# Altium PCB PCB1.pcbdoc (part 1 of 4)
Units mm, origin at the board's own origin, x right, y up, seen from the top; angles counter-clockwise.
Board outline 77.9 x 109.02 mm, 4 copper layers (Top Layer, Inner1, Inner2, Bottom Layer); 129 components, 135 nets, 715 pads, 425 vias.
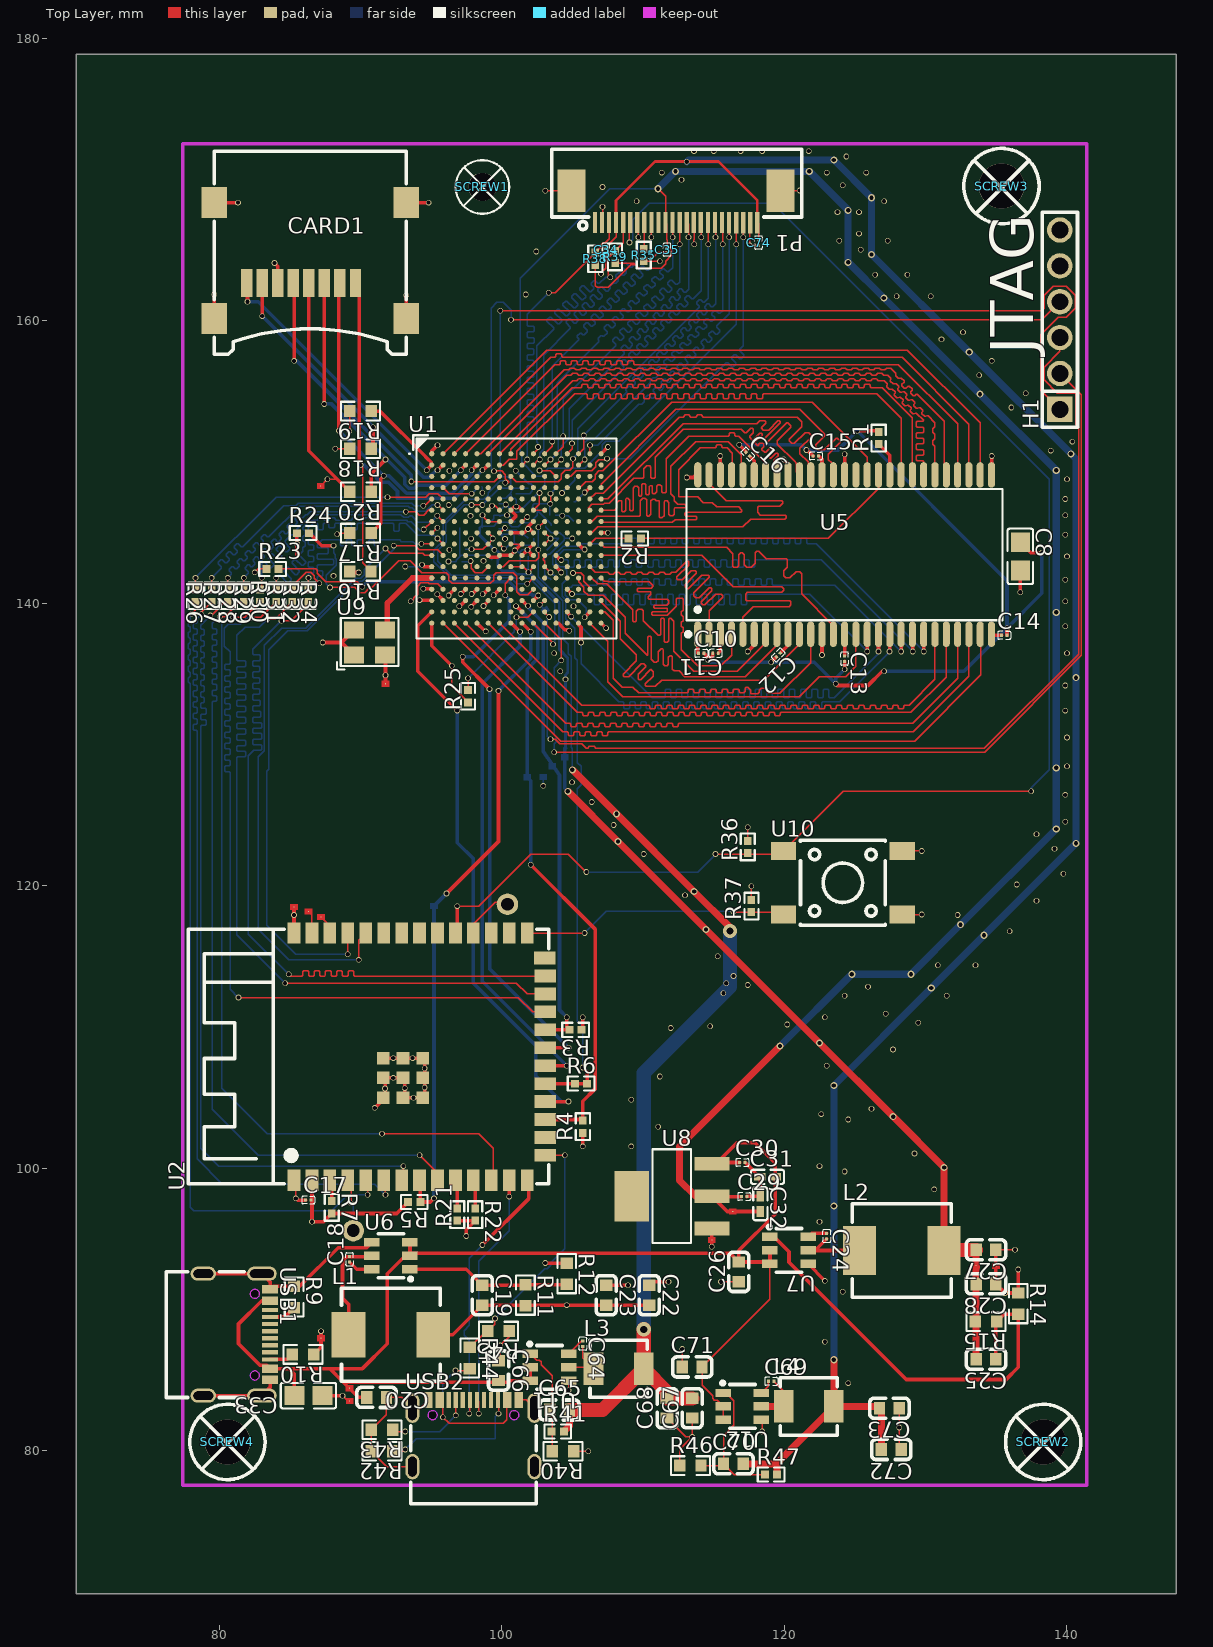
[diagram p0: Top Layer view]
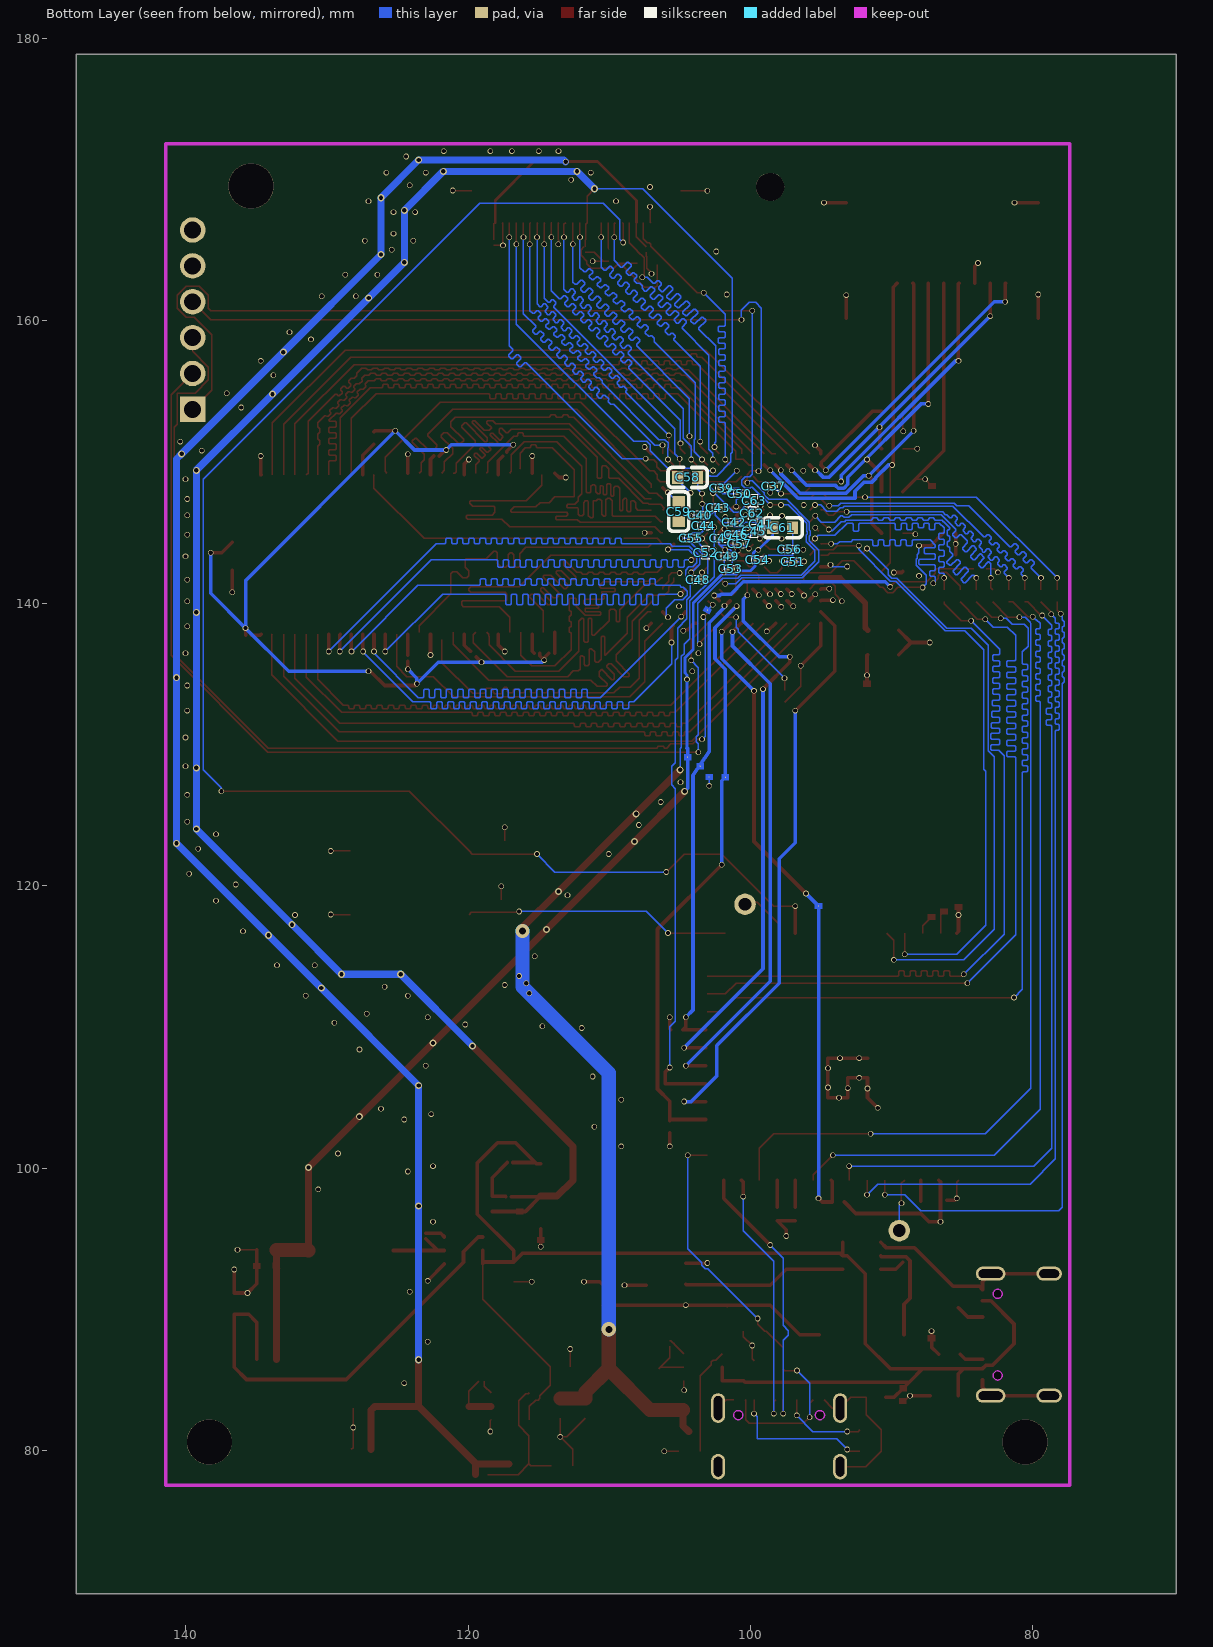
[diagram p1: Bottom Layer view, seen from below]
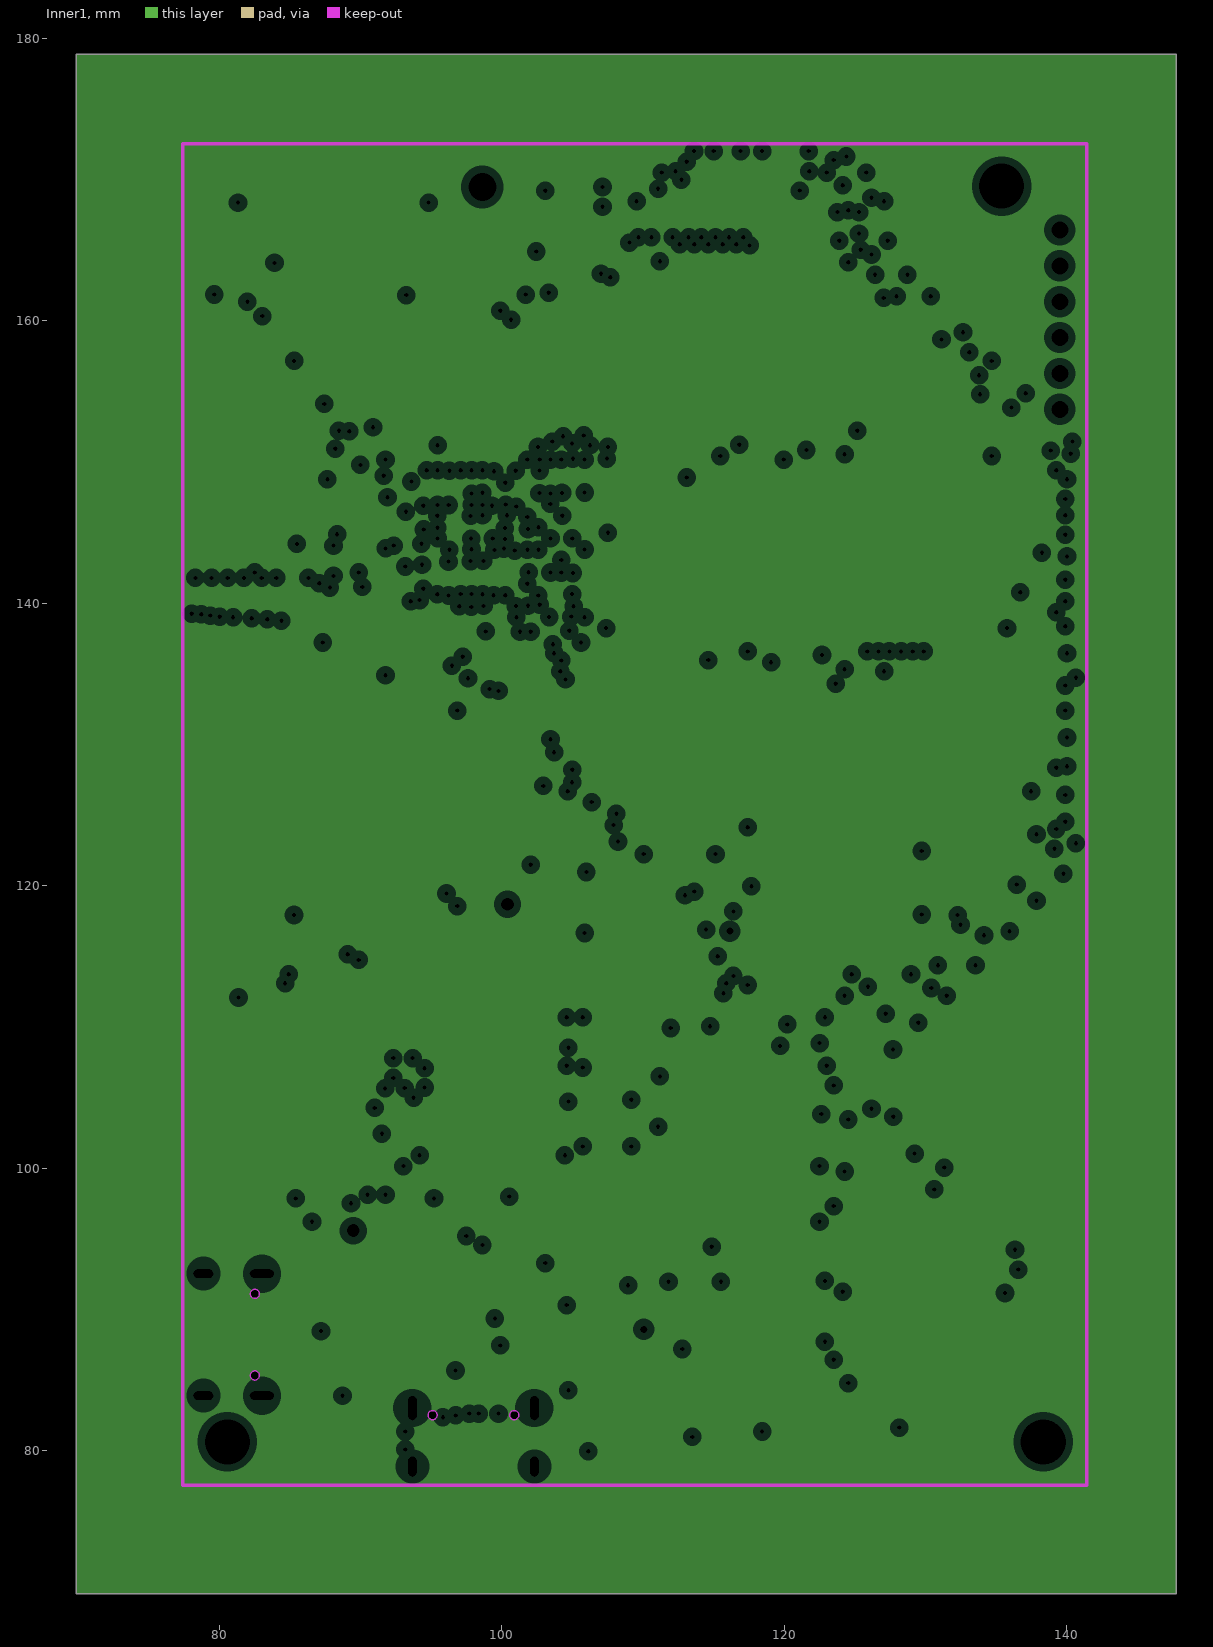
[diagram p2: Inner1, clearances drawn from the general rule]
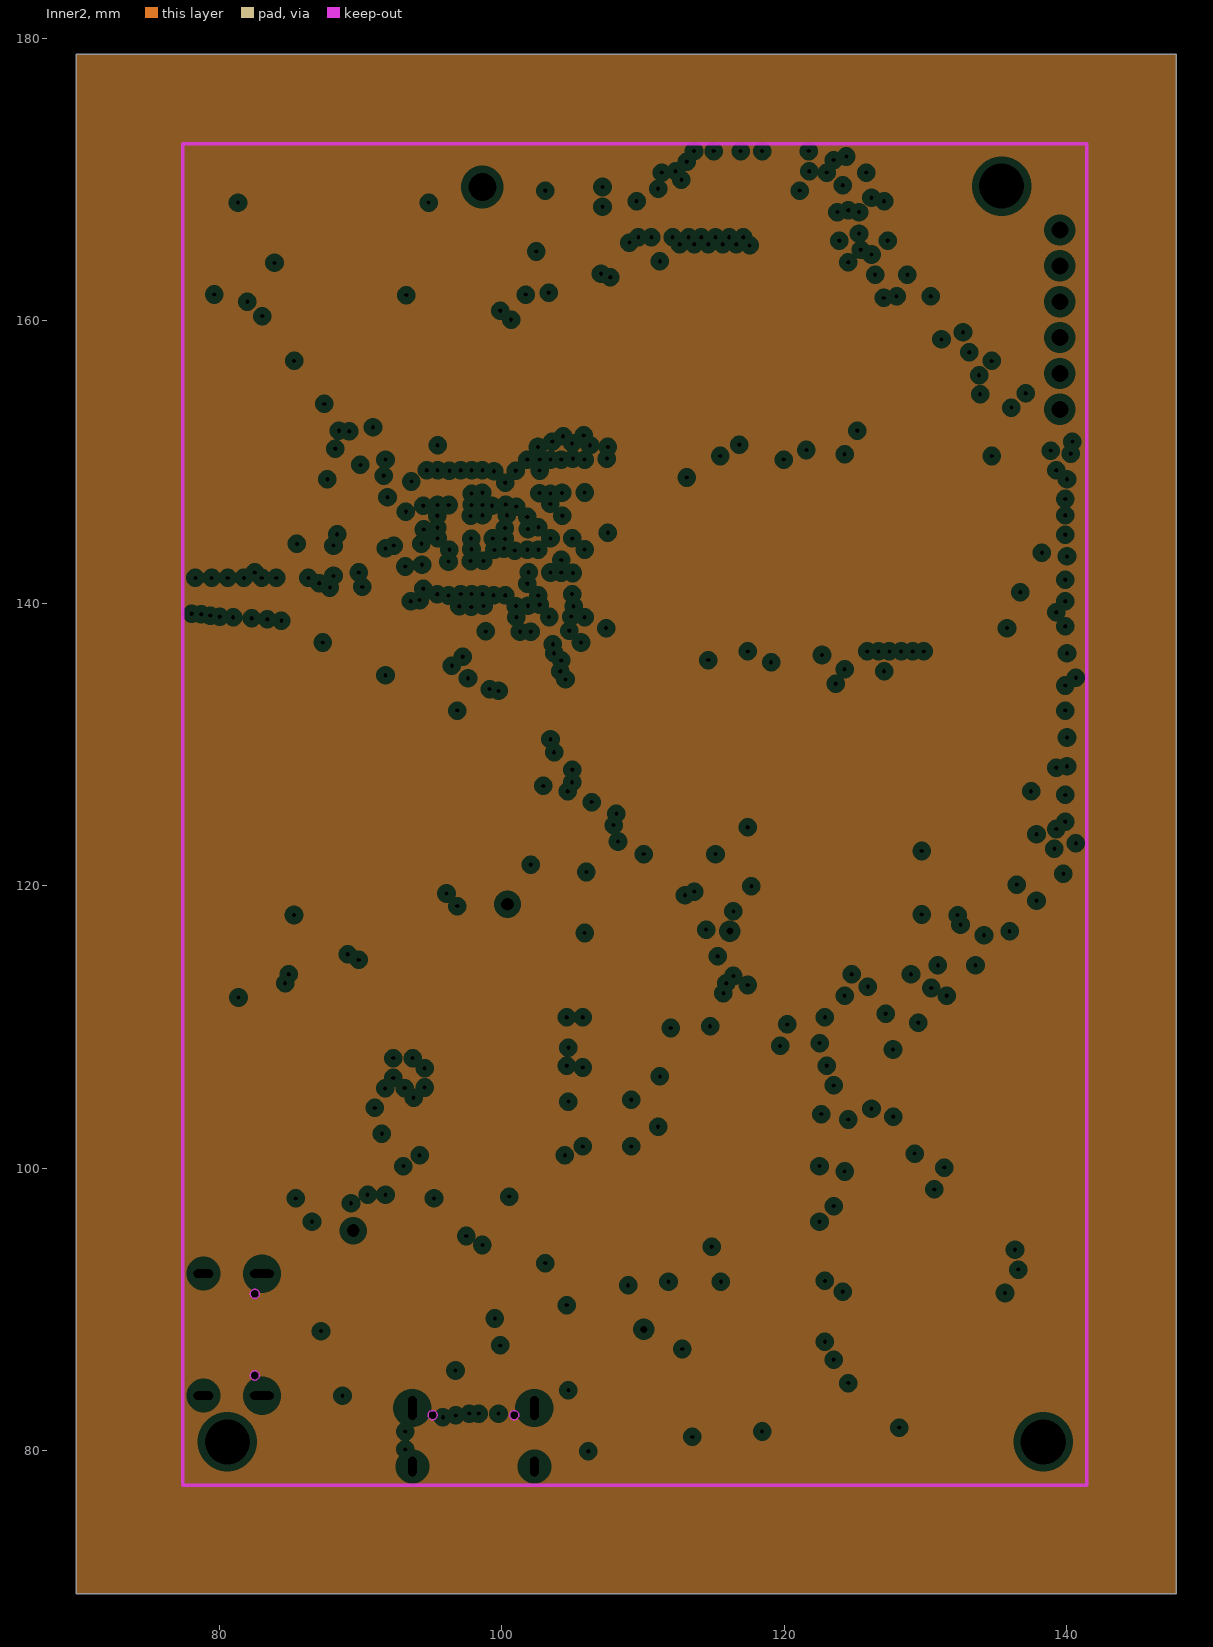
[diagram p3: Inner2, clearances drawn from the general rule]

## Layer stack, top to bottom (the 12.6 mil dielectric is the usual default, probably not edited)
Top Layer: signal copper (thickness not stored)
Dielectric: dielectric 0.32, FR-4, Dk 4.8
Inner1: plane copper (thickness not stored)
Dielectric: dielectric 0.32, FR-4, Dk 4.8
Inner2: plane copper (thickness not stored)
Dielectric: dielectric 0.32, FR-4, Dk 4.8
Bottom Layer: signal copper (thickness not stored)

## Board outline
147.752,69.85 69.85,69.85 69.85,178.875 147.752,178.875

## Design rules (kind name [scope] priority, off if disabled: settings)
BoardOutlineClearance copperThickness1oz [All] p0: genericclearance=0.254 ignorepadtopadclearanceinfootprint=FALSE except(0: Arc-SplitContinuation Track-SplitContinuation SMDPad-SplitContinuation THPad-SplitContinuation Via-SplitContinuation Fill-SplitContinuation Poly-SplitContinuation Region-SplitContinuation Text-SplitContinuation; 0.152: Track-CutoutEdge SMDPad-CutoutEdge THPad-CutoutEdge Via-CutoutEdge Region-CutoutEdge; 0.3: Track-OutlineEdge SMDPad-OutlineEdge THPad-OutlineEdge Via-OutlineEdge Fill-OutlineEdge Region-OutlineEdge Poly-OutlineEdge Text-OutlineEdge Fill-CutoutEdge)
BoardOutlineClearance copperThickness2oz [All] p0: genericclearance=0.254 ignorepadtopadclearanceinfootprint=FALSE except(0: Arc-SplitContinuation Track-SplitContinuation SMDPad-SplitContinuation THPad-SplitContinuation Via-SplitContinuation Fill-SplitContinuation Poly-SplitContinuation Region-SplitContinuation Text-SplitContinuation; 0.152: Track-CutoutEdge SMDPad-CutoutEdge THPad-CutoutEdge Via-CutoutEdge Region-CutoutEdge; 0.3: Track-OutlineEdge SMDPad-OutlineEdge THPad-OutlineEdge Via-OutlineEdge Fill-OutlineEdge Region-OutlineEdge Poly-OutlineEdge Text-OutlineEdge Fill-CutoutEdge)
Clearance copperThickness1oz [(InNet('SD_A0') OR InNet('SD_A1') OR InNet('SD_A2') OR InNet('SD_A3') OR InNet('SD_A4') OR InNet('SD_A5') OR InNet('SD_A6') OR InNet('SD_A7') OR InNet('SD_A8') OR InNet('SD_A9') OR InNet('SD_A10') OR InNet('SD_A11') OR InNet('SD_A12') OR InNet('SD_DQ15') OR InNet('SD_DQ14') OR InNet('SD_DQ8') OR InNet('SD_BA0') OR InNet('SD_BA1') OR InNet('SD_DQ9') OR InNet('SD_DQ7') OR InNet('SD_CLK') OR InNet('SD_WE_N') OR InNet('SD_DQ10') OR InNet('SD_CAS_N') OR InNet('SD_DQM1') OR InNet('SD_DQ2') OR InNet('SD_DQ3') OR InNet('SD_DQ11') OR InNet('SD_DQ12') OR InNet('SD_DQ13') OR InNet('SD_DQ0') OR InNet('SD_DQ1') OR InNet('SD_CS_N') OR InNet('SD_RAS_N') OR InNet('SD_DQ4') OR InNet('SD_DQ6') OR InNet('$1N9241') OR InNet('$1N9192') OR InNet('GND') OR InNet('$1N9142') OR InNet('SD_DQ5') OR InNet('$1N9091') OR InNet('SD_DQM0') OR InNet('$1N9039') OR InNet('$1N8986') OR InNet('$1N8318') OR InNet('$1N9437') OR InNet('$1N9341') OR InNet('+3V3') OR InNet('$1N11348') OR InNet('DOUT') OR InNet('DIN') OR InNet('CCLK') OR InNet('DONE') OR InNet('PROGRAMN') OR InNet('INITN') OR InNet('$1N11975') OR InNet('DN') OR InNet('DP') OR InNet('$1N14459') OR InNet('$1N14416') OR InNet('$1N14567') OR InNet('+5V') OR InNet('$1N16833') OR InNet('$1N16832') OR InNet('+1V1') OR InNet('$1N16834') OR InNet('+1V8') OR InNet('$1N17349') OR InNet('$1N12557') OR InNet('$1N12553') OR InNet('M_D2') OR InNet('M_D3') OR InNet('M_CMD') OR InNet('M_CLK') OR InNet('M_D0') OR InNet('M_D1') OR InNet('SDA') OR InNet('SCL') OR InNet('RESET') OR InNet('VSYNC') OR InNet('HREF') OR InNet('Y9') OR InNet('MCLK') OR InNet('Y8') OR InNet('Y7') OR InNet('PCLK') OR InNet('Y6') OR InNet('Y2') OR InNet('Y5') OR InNet('Y3') OR InNet('Y4') OR InNet('CRYSTAL') OR InNet('SSPI_CS_N') OR InNet('D0') OR InNet('D1') OR InNet('D2') OR InNet('D4') OR InNet('D3') OR InNet('D5') OR InNet('D6') OR InNet('D7') OR InNet('RX') OR InNet('TX') OR InNet('$1N29790') OR InNet('$1N29833') OR InNet('$1N29916') OR InNet('$1N29959') OR InNet('$1N30002') OR InNet('$1N30085') OR InNet('$1N30089') OR InNet('$1N30093') OR InNet('TDO') OR InNet('TDI') OR InNet('TMS') OR InNet('TCK') OR InNet('$1N33205') OR InNet('PROGRAM') OR InNet('$2N5507') OR InNet('$2N5509') OR InNet('$2N5511') OR InNet('FSDA') OR InNet('FSCL') OR InNet('+2V5') OR InNet('$1N60668') OR InNet('$1N60669') OR InNet('$1N60670') OR InNet('USB_VBUS') OR InNet('$1N63772') OR InNet('$1N63749') OR InNet('$1N63825') OR InNet('+2V8') OR InNet('$1N64402') OR InNet('$1N64401') OR InNet('$1N64403'))] p1: gap=0.178 ignorepadtopadclearanceinfootprint=FALSE except(0.099: Track-Track; 0.152: Track-SMDPad SMDPad-SMDPad Track-THPad SMDPad-THPad THPad-THPad Track-Via SMDPad-Via THPad-Via Via-Via SMDPad-Fill THPad-Fill Via-Fill Fill-Fill Track-Region SMDPad-Region THPad-Region Via-Region Region-Region Track-Poly SMDPad-Poly THPad-Poly Via-Poly Fill-Poly Region-Poly Poly-Poly Track-Text SMDPad-Text THPad-Text Via-Text Fill-Text Region-Text Poly-Text Text-Text; 0.175: Track-Hole SMDPad-Hole THPad-Hole Via-Hole Fill-Hole Region-Hole Poly-Hole Text-Hole Sheet-Hole; 0.3: Track-Fill Fill-Region Track-Sheet SMDPad-Sheet THPad-Sheet Via-Sheet Fill-Sheet Region-Sheet Poly-Sheet Text-Sheet)
Clearance copperThickness2oz [All] p1: gap=0.178 ignorepadtopadclearanceinfootprint=FALSE except(0.152: Track-SMDPad SMDPad-SMDPad Track-THPad SMDPad-THPad THPad-THPad Track-Via SMDPad-Via THPad-Via Via-Via SMDPad-Fill THPad-Fill Via-Fill Fill-Fill Track-Region SMDPad-Region THPad-Region Via-Region Region-Region Track-Poly SMDPad-Poly THPad-Poly Via-Poly Fill-Poly Region-Poly Poly-Poly Track-Text SMDPad-Text THPad-Text Via-Text Fill-Text Region-Text Poly-Text Text-Text; 0.175: Track-Hole SMDPad-Hole THPad-Hole Via-Hole Fill-Hole Region-Hole Poly-Hole Text-Hole Sheet-Hole; 0.203: Track-Track; 0.3: Track-Fill Fill-Region Track-Sheet SMDPad-Sheet THPad-Sheet Via-Sheet Fill-Sheet Region-Sheet Poly-Sheet Text-Sheet)
DiffPairsRouting differentialPair [All] p1: maxuncoupledlength=10 minlimit=6 maxlimit=6 mostfreqgap=6 toplayer_minwidth=5 toplayer_prefwidth=10 toplayer_maxwidth=100 bottomlayer_minwidth=5 bottomlayer_prefwidth=10 bottomlayer_maxwidth=100
PasteMaskExpansion pasteMaskExpansion [All] p1: expansion=0
PlaneConnect innerPlane [All] p1: planeconnectstyle=Relief reliefexpansion=0.508 reliefentries=4 reliefconductorwidth=0.254 reliefairgap=0.254
PolygonConnect copperRegion [All] p1: connectstyle=Relief reliefentries=4 reliefconductorwidth=10 polygonreliefangle="90 Angle" airgapwidth=10
RoutingVias viaSize [All] p1: viastyle="Through Hole" holewidth=11.811 minholewidth=11.811 maxholewidth=248.0314 width=15.748 minwidth=15.748 maxwidth=393.7008
SolderMaskExpansion solderMaskExpansion [All] p1: useseparateexpansions=TRUE expansion=2 expansionbottom=2
Width copperThickness1oz [All] p1: maxlimit=100 minlimit=4 preferedwidth=4
Width copperThickness2oz [All] p1: maxlimit=100 minlimit=8 preferedwidth=10

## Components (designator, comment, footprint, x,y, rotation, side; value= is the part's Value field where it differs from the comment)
C8 "CL21A476MQYNNNE" C0805 136.711,143.315 r270 top
C10 "GRM022R60J104KE15D" C01005 114.105,136.457 r0 top
C11 "GRM022R60J104KE15D" C01005 115.121,136.457 r180 top
C12 "GRM022R60J104KE15D" C01005 119.566,136.33 r225 top
C13 "GRM022R60J104KE15D" C01005 124.265,136.076 r270 top
C14 "GRM022R60J104KE15D" C01005 135.568,137.727 r0 top
C15 "GRM022R60J104KE15D" C01005 122.233,150.427 r0 top
C16 "GRM022R60J104KE15D" C01005 117.407,150.554 r315 top
C17 "GRM022R60J104KE15D" C01005 86.292,97.722 r0 top
C18 "GRM022R60J104KE15D" C01005 89.213,93.531 r90 top
C19 "TCC0603X7R104K500CT" C0603 98.611,90.991 r270 top
C20 "TCC0603X5R226M6R3CT" C0603 91.118,83.752 r180 top
C22 "TCC0603X5R226M6R3CT" C0603 110.422,90.991 r270 top
C23 "TCC0603X5R226M6R3CT" C0603 107.374,90.991 r270 top
C24 "GRM022R60J104KE15D" C01005 122.995,95.182 r270 top
C25 "TCC0603X7R104K500CT" C0603 134.277,86.458 r180 top
C26 "TCC0603X5R226M6R3CT" C0603 116.772,92.642 r90 top
C27 "TCC0603X5R226M6R3CT" C0603 134.277,94.205 r180 top
C28 "TCC0603X5R226M6R3CT" C0603 134.277,91.792 r180 top
C29 "GRM022R60J104KE15D" C01005 117.153,97.976 r0 top
C30 "GRM022R60J104KE15D" C01005 117.026,100.389 r0 top
C31 "GRM155R60J106ME44D" C0402 118.804,99.373 r0 top
C32 "GRM155R60J106ME44D" C0402 118.296,97.468 r270 top
C33 "CL21A476MQYNNNE" C0805 86.292,83.879 r180 top
C34 "GRM022R60J104KE15D" C01005 107.374,165.032 r270 top
C35 "GRM022R60J104KE15D" C01005 111.692,165.032 r270 top
C37 "GRM022R60J104KE15D" C01005 98.357,148.268 r180 bottom
C39 "GRM022R60J104KE15D" C01005 102.04,148.141 r180 bottom
C40 "GRM022R60J104KE15D" C01005 103.564,146.236 r180 bottom
C41 "GRM022R60J104KE15D" C01005 99.246,145.601 r90 bottom
C42 "GRM022R60J104KE15D" C01005 101.151,145.728 r180 bottom
C43 "GRM022R60J104KE15D" C01005 102.294,146.744 r180 bottom
C44 "GRM022R60J104KE15D" C01005 103.31,145.474 r180 bottom
C45 "GRM022R60J104KE15D" C01005 99.754,145.093 r270 bottom
C46 "GRM022R60J104KE15D" C01005 101.024,144.839 r180 bottom
C47 "GRM022R60J104KE15D" C01005 102.04,144.585 r0 bottom
C48 "GRM022R60J104KE15D" C01005 103.691,141.664 r180 bottom
C49 "GRM022R60J104KE15D" C01005 101.659,143.315 r180 bottom
C50 "GRM022R60J104KE15D" C01005 100.77,147.76 r180 bottom
C51 "GRM022R60J104KE15D" C01005 96.96,142.934 r180 bottom
C52 "GRM022R60J104KE15D" C01005 103.183,143.569 r270 bottom
C53 "GRM022R60J104KE15D" C01005 101.405,142.426 r180 bottom
C54 "GRM022R60J104KE15D" C01005 99.5,143.061 r180 bottom
C55 "GRM022R60J104KE15D" C01005 104.199,144.585 r0 bottom
C56 "GRM022R60J104KE15D" C01005 97.214,143.823 r180 bottom
C57 "GRM022R60J104KE15D" C01005 100.77,144.204 r0 bottom
C58 "TCC0603X5R226M6R3CT" C0603 104.453,148.903 r180 bottom
C59 "TCC0603X5R226M6R3CT" C0603 105.088,146.49 r90 bottom
C61 "TCC0603X5R226M6R3CT" C0603 97.722,145.347 r180 bottom
C62 "GRM022R60J104KE15D" C01005 99.881,146.363 r270 bottom
C63 "GRM022R60J104KE15D" C01005 99.754,147.252 r90 bottom
C64 "GRM022R60J104KE15D" C01005 105.723,87.562 r270 top
C65 "TCC0603X7R104K500CT" C0603 104.072,82.863 r0 top
C66 "TCC0603X5R226M6R3CT" C0603 99.754,85.657 r270 top
C67 "TCC0603X5R226M6R3CT" C0603 113.47,82.99 r90 top
C68 "TCC0603X5R226M6R3CT" C0603 111.692,82.99 r90 top
C69 "GRM022R60J104KE15D" C01005 119.058,84.895 r0 top
C70 "TCC0603X7R104K500CT" C0603 116.391,79.053 r0 top
C71 "TCC0603X5R226M6R3CT" C0603 113.47,85.911 r0 top
C72 "TCC0603X5R226M6R3CT" C0603 127.567,80.069 r180 top
C73 "TCC0603X5R226M6R3CT" C0603 127.44,82.99 r180 top
C74 "GRM022R60J104KE15D" C01005 118.169,165.54 r270 top
CARD1 "DS1139-06-08SS4BSR" TF-SMD_DS1139-06-08SS4BSR 86.419,164.27 r0 top
H1 "2.54-1x6P直针" HDR-TH_6P-P2.54-V-M-1 139.505,160.079 r90 top
L1 "FXL0630-6R8-M" IND-SMD_L7.0-W6.6 92.134,88.197 r0 top
L2 "FXL0630-100-M" IND-SMD_L7.3-W6.8 128.313,94.16 r0 top
L3 "SL0420-3R3M" IND-SMD_L4.5-W4.1_SL0420 108.263,85.784 r0 top
L4 "SL0420-3R3M" IND-SMD_L4.5-W4.1_SL0420 121.725,83.117 r0 top
P1 "AFC07-S24FCC-00" FPC-SMD_AFC07-S24FCC-00 112.327,168.08 r180 top
R1 "0402WGF1002TCE" R0402 126.678,151.697 r90 top
R2 "0402WGF330JTCE" R0402 109.406,144.585 r180 top
R3 "0402WGF1002TCE" R0402 105.215,109.787 r180 top
R4 "0402WGF1002TCE" R0402 105.723,102.929 r90 top
R5 "0402WGF1002TCE" R0402 93.785,97.595 r180 top
R6 "0402WGF330JTCE" R0402 105.596,105.977 r0 top
R7 "0402WGF1002TCE" R0402 87.943,97.214 r270 top
R9 "0603WAF5101T5E" R0603 85.276,90.864 r270 top
R10 "0603WAF5101T5E" R0603 85.911,86.8 r180 top
R11 "FRC0603F1963TS" R0603 101.659,90.991 r270 top
R12 "FRC0603F6202TS" R0603 104.58,92.515 r270 top
R14 "FRC0603F6202TS" R0603 136.563,90.395 r270 top
R15 "0603WAF2322T5E" R0603 134.277,89.125 r180 top
R16 "FRC0603F6202TS" R0603 89.971,142.247 r180 top
R17 "FRC0603F6202TS" R0603 89.975,144.966 r180 top
R18 "FRC0603F6202TS" R0603 89.975,150.935 r180 top
R19 "FRC0603F6202TS" R0603 89.975,153.602 r180 top
R20 "FRC0603F6202TS" R0603 89.975,147.887 r180 top
R21 "0402WGF1002TCE" R0402 96.833,96.706 r270 top
R22 "0402WGF1002TCE" R0402 98.103,96.706 r270 top
R23 "0402WGF1002TCE" R0402 83.752,142.426 r0 top
R24 "0402WGF1002TCE" R0402 85.911,144.966 r0 top
R25 "0402WGF1002TCE" R0402 97.595,133.409 r90 top
R26 "0402WGF330JTCE" R0402 78.291,140.521 r270 top
R27 "0402WGF330JTCE" R0402 79.434,140.521 r270 top
R28 "0402WGF330JTCE" R0402 80.577,140.521 r270 top
R29 "0402WGF330JTCE" R0402 81.72,140.521 r270 top
R30 "0402WGF330JTCE" R0402 82.863,140.521 r270 top
R31 "0402WGF330JTCE" R0402 84.006,140.521 r270 top
R32 "0402WGF330JTCE" R0402 85.149,140.521 r270 top
R34 "0402WGF330JTCE" R0402 86.292,140.521 r270 top
R35 "0402WGF1002TCE" R0402 110.041,164.651 r270 top
R36 "0402WGF1002TCE" R0402 117.407,122.741 r90 top
R37 "0402WGF1002TCE" R0402 117.661,118.55 r90 top
R38 "0402WGF1002TCE" R0402 106.612,164.397 r270 top
R39 "0402WGF1002TCE" R0402 108.009,164.524 r270 top
R40 "FRC0603F6202TS" R0603 104.326,79.942 r180 top
R41 "RC0402FR-07130KL" R0402 103.945,81.339 r0 top
R42 "0603WAF5101T5E" R0603 91.499,79.942 r180 top
R43 "0603WAF5101T5E" R0603 91.499,81.466 r180 top
R44 "FRC0603F1963TS" R0603 97.722,86.546 r270 top
R45 "FRC0603F1963TS" R0603 99.754,88.451 r180 top
R46 "FRC0603F6202TS" R0603 113.343,78.926 r0 top
R47 "0402WGF1543TCE" R0402 119.058,78.291 r0 top
SCREW1 "Screw-Hole-M2" Screw-Hole-M2 98.611,169.477 r0 top
SCREW2 "Screw-Hole-M3" Screw-Hole-M3 138.389,80.535 r0 top
SCREW3 "Screw-Hole-M3" Screw-Hole-M3 135.441,169.477 r0 top
SCREW4 "Screw-Hole-M3" Screw-Hole-M3 80.619,80.535 r0 top
U1 "LFE5U-25F-6BG256C" CABGA-256_L14.0-W14.0-R16-C16-P0.80-TL 101.024,144.585 r0 top
U2 "ESP32-S3-WROOM-1-N16R2" WIRELM-SMD_ESP32-S3-WROOM-1 94.166,107.882 r90 top
U5 "W9825G6KH-6" TSOP-54_L22.2-W10.2-P0.80-LS11.8-BL 124.265,143.442 r0 top
U6 "AP63200WU-7" SOT-23-6_L2.9-W1.6-P0.95-LS2.8-BR 92.134,93.785 r0 top
U7 "AP63200WU-7" SOT-23-6_L2.9-W1.6-P0.95-LS2.8-BR 120.328,94.166 r180 top
U8 "AMS1117-1.8_C6185" SOT-223-4_L6.5-W3.5-P2.30-LS7.0-BR 112.026,98.005 r0 top
U9 "XOS32024000LT00351005" OSC-SMD_4P-L3.2-W2.5-BL 90.61,137.219 r0 top
U10 "TPS645-5NC60" SW-SMD_4P-L6.0-W6.0-P4.50-LS9.2 124.138,120.201 r0 top
U11 "AP63200WU-7" SOT-23-6_L2.9-W1.6-P0.95-LS2.8-BR 103.363,85.883 r180 top
U12 "AP63200WU-7" SOT-23-6_L2.9-W1.6-P0.95-LS2.8-BR 117.026,83.117 r180 top
USB1 "TYPE-C16PIN" USB-C-SMD_TYPE-C16PIN#1 81.212,88.197 r270 top
USB2 "TYPE-C16PIN" USB-C-SMD_TYPE-C16PIN#2 97.976,81.212 r0 top

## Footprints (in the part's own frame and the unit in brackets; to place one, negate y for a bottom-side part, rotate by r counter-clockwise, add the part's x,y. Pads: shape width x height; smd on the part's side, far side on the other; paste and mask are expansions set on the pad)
C0402 [mm]
  rect 0.79x0.54 smd: 1(-0.545,0) 2(0.545,0)
  silkscreen extent -1.17,-0.5 1.17,0.5
C0603 [mm]
  rect 0.8x0.9 smd: 1(-0.7,0) 2(0.7,0)
  silkscreen extent -1.39,-0.71 1.39,0.71
C0805 [mm]
  rect 1.41x1.35 smd: 1(-1,0) 2(1,0)
  silkscreen extent -1.96,-0.9 1.96,0.9
C01005 [mm]
  rect 0.21x0.22 smd: 1(-0.195,0) 2(0.195,0)
  silkscreen extent -0.46,-0.27 0.46,0.27
CABGA-256_L14.0-W14.0-R16-C16-P0.80-TL [mm]
  round 0.36 smd: A1(-6,6) A2(-5.2,6) A3(-4.4,6) A4(-3.6,6) A5(-2.8,6) A6(-2,6) A7(-1.2,6) A8(-0.4,6) A9(0.4,6) A10(1.2,6) A11(2,6) A12(2.8,6) A13(3.6,6) A14(4.4,6) A15(5.2,6) A16(6,6) B1(-6,5.2) B2(-5.2,5.2) B3(-4.4,5.2) B4(-3.6,5.2) B5(-2.8,5.2) B6(-2,5.2) B7(-1.2,5.2) B8(-0.4,5.2) B9(0.4,5.2) B10(1.2,5.2) B11(2,5.2) B12(2.8,5.2) B13(3.6,5.2) B14(4.4,5.2) B15(5.2,5.2) B16(6,5.2) C1(-6,4.4) C2(-5.2,4.4) C3(-4.4,4.4) C4(-3.6,4.4) C5(-2.8,4.4) C6(-2,4.4) C7(-1.2,4.4) C8(-0.4,4.4) C9(0.4,4.4) C10(1.2,4.4) C11(2,4.4) C12(2.8,4.4) C13(3.6,4.4) C14(4.4,4.4) C15(5.2,4.4) C16(6,4.4) D1(-6,3.6) D2(-5.2,3.6) D3(-4.4,3.6) D4(-3.6,3.6) D5(-2.8,3.6) D6(-2,3.6) D7(-1.2,3.6) D8(-0.4,3.6) D9(0.4,3.6) D10(1.2,3.6) D11(2,3.6) D12(2.8,3.6) D13(3.6,3.6) D14(4.4,3.6) D15(5.2,3.6) D16(6,3.6) E1(-6,2.8) E2(-5.2,2.8) E3(-4.4,2.8) E4(-3.6,2.8) E5(-2.8,2.8) E6(-2,2.8) E7(-1.2,2.8) E8(-0.4,2.8) E9(0.4,2.8) E10(1.2,2.8) E11(2,2.8) E12(2.8,2.8) E13(3.6,2.8) E14(4.4,2.8) E15(5.2,2.8) E16(6,2.8) F1(-6,2) F2(-5.2,2) F3(-4.4,2) F4(-3.6,2) F5(-2.8,2) F6(-2,2) F7(-1.2,2) F8(-0.4,2) F9(0.4,2) F10(1.2,2) F11(2,2) F12(2.8,2) F13(3.6,2) F14(4.4,2) F15(5.2,2) F16(6,2) G1(-6,1.2) G2(-5.2,1.2) G3(-4.4,1.2) G4(-3.6,1.2) G5(-2.8,1.2) G6(-2,1.2) G7(-1.2,1.2) G8(-0.4,1.2) G9(0.4,1.2) G10(1.2,1.2) G11(2,1.2) G12(2.8,1.2) G13(3.6,1.2) G14(4.4,1.2) G15(5.2,1.2) G16(6,1.2) H1(-6,0.4) H2(-5.2,0.4) H3(-4.4,0.4) H4(-3.6,0.4) H5(-2.8,0.4) H6(-2,0.4) H7(-1.2,0.4) H8(-0.4,0.4) H9(0.4,0.4) H10(1.2,0.4) H11(2,0.4) H12(2.8,0.4) H13(3.6,0.4) H14(4.4,0.4) H15(5.2,0.4) H16(6,0.4) J1(-6,-0.4) J2(-5.2,-0.4) J3(-4.4,-0.4) J4(-3.6,-0.4) J5(-2.8,-0.4) J6(-2,-0.4) J7(-1.2,-0.4) J8(-0.4,-0.4) J9(0.4,-0.4) J10(1.2,-0.4) J11(2,-0.4) J12(2.8,-0.4) J13(3.6,-0.4) J14(4.4,-0.4) J15(5.2,-0.4) J16(6,-0.4) K1(-6,-1.2) K2(-5.2,-1.2) K3(-4.4,-1.2) K4(-3.6,-1.2) K5(-2.8,-1.2) K6(-2,-1.2) K7(-1.2,-1.2) K8(-0.4,-1.2) K9(0.4,-1.2) K10(1.2,-1.2) K11(2,-1.2) K12(2.8,-1.2) K13(3.6,-1.2) K14(4.4,-1.2) K15(5.2,-1.2) K16(6,-1.2) L1(-6,-2) L2(-5.2,-2) L3(-4.4,-2) L4(-3.6,-2) L5(-2.8,-2) L6(-2,-2) L7(-1.2,-2) L8(-0.4,-2) L9(0.4,-2) L10(1.2,-2) L11(2,-2) L12(2.8,-2) L13(3.6,-2) L14(4.4,-2) L15(5.2,-2) L16(6,-2) M1(-6,-2.8) M2(-5.2,-2.8) M3(-4.4,-2.8) M4(-3.6,-2.8) M5(-2.8,-2.8) M6(-2,-2.8) M7(-1.2,-2.8) M8(-0.4,-2.8) M9(0.4,-2.8) M10(1.2,-2.8) M11(2,-2.8) M12(2.8,-2.8) M13(3.6,-2.8) M14(4.4,-2.8) M15(5.2,-2.8) M16(6,-2.8) N1(-6,-3.6) N2(-5.2,-3.6) N3(-4.4,-3.6) N4(-3.6,-3.6) N5(-2.8,-3.6) N6(-2,-3.6) N7(-1.2,-3.6) N8(-0.4,-3.6) N9(0.4,-3.6) N10(1.2,-3.6) N11(2,-3.6) N12(2.8,-3.6) N13(3.6,-3.6) N14(4.4,-3.6) N15(5.2,-3.6) N16(6,-3.6) P1(-6,-4.4) P2(-5.2,-4.4) P3(-4.4,-4.4) P4(-3.6,-4.4) P5(-2.8,-4.4) P6(-2,-4.4) P7(-1.2,-4.4) P8(-0.4,-4.4) P9(0.4,-4.4) P10(1.2,-4.4) P11(2,-4.4) P12(2.8,-4.4) P13(3.6,-4.4) P14(4.4,-4.4) P15(5.2,-4.4) P16(6,-4.4) R1(-6,-5.2) R2(-5.2,-5.2) R3(-4.4,-5.2) R4(-3.6,-5.2) R5(-2.8,-5.2) R6(-2,-5.2) R7(-1.2,-5.2) R8(-0.4,-5.2) R9(0.4,-5.2) R10(1.2,-5.2) R11(2,-5.2) R12(2.8,-5.2) R13(3.6,-5.2) R14(4.4,-5.2) R15(5.2,-5.2) R16(6,-5.2) T1(-6,-6) T2(-5.2,-6) T3(-4.4,-6) T4(-3.6,-6) T5(-2.8,-6) T6(-2,-6) T7(-1.2,-6) T8(-0.4,-6) T9(0.4,-6) T10(1.2,-6) T11(2,-6) T12(2.8,-6) T13(3.6,-6) T14(4.4,-6) T15(5.2,-6) T16(6,-6)
  silkscreen extent -7.63,-7.08 7.08,7.3
FPC-SMD_AFC07-S24FCC-00 [mm]
  rect 0.3x1.5 smd: 1(5.745,1.129) 2(5.245,1.129) 3(4.746,1.129) 4(4.245,1.129) 5(3.746,1.129) 6(3.245,1.129) 7(2.746,1.129) 8(2.245,1.129) 9(1.746,1.129) 10(1.245,1.129) 11(0.746,1.129) 12(0.245,1.129) 13(-0.254,1.129) 14(-0.755,1.129) 15(-1.251,1.13) 16(-1.754,1.13) 17(-2.254,1.128) 18(-2.754,1.129) 19(-3.254,1.129) 20(-3.756,1.132) 21(-4.256,1.132) 22(-4.756,1.132) 23(-5.256,1.132) 24(-5.756,1.132)
  rect 2x3 smd: 25(-7.401,-1.132) 26(7.401,-1.125)
  silkscreen extent -8.89,-4.07 8.8,1.61
HDR-TH_6P-P2.54-V-M-1 [mm]
  rect 1.8x1.8 hole 1.2: 1(-6.35,0)
  round 1.8 hole 1.2: 2(-3.81,0) 3(-1.27,0) 4(1.27,0) 5(3.81,0) 6(6.35,0)
  silkscreen extent -7.62,-1.25 7.62,1.25
IND-SMD_L4.5-W4.1_SL0420 [mm]
  rect 1.4x2.3 smd: 1(-1.775,0) 2(1.775,0)
  silkscreen extent -2.03,-2.03 2.03,2.03
IND-SMD_L7.0-W6.6 [mm]
  rect 2.4x3.2 smd: 1(-3,0) 2(3,0)
  silkscreen extent -3.5,-3.3 3.5,3.3
IND-SMD_L7.3-W6.8 [mm]
  rect 2.35x3.5 smd: 1(-3,0) 2(3,0)
  silkscreen extent -3.5,-3.3 3.5,3.3
OSC-SMD_4P-L3.2-W2.5-BL [mm]
  rect 1.4x1.2 smd: 1(-1.1,-0.875) 2(1.1,-0.875) 3(1.1,0.875) 4(-1.1,0.875)
  silkscreen extent -2.29,-1.9 2.07,1.72
R0402 [mm]
  rect 0.566x0.54 smd: 1(-0.433,0) 2(0.433,0)
  silkscreen extent -0.94,-0.5 0.94,0.5
R0603 [mm]
  rect 0.806x0.864 smd: 1(-0.753,0) 2(0.753,0)
  silkscreen extent -1.39,-0.66 1.39,0.66
Screw-Hole-M2 [mm]
  round 2 hole 2: 1(0,0)
  silkscreen extent -1.9,-1.9 1.9,1.9
Screw-Hole-M3 [mil]
  round 126 hole 126: 1(-2.5,2.5)
  silkscreen extent -107,-102 102,107
SOT-23-6_L2.9-W1.6-P0.95-LS2.8-BR [mm]
  rect 1.1x0.6 smd: 1(1.35,-0.95) 2(1.35,0) 3(1.35,0.95) 4(-1.35,0.95) 5(-1.35,0) 6(-1.35,-0.95)
  silkscreen extent -0.9,-1.78 1.52,1.55
SOT-223-4_L6.5-W3.5-P2.30-LS7.0-BR [mm]
  rect 2.47x0.98 smd: 1(2.835,-2.3) 2(2.835,0) 3(2.835,2.3)
  rect 2.47x3.6 smd: 4(-2.835,0)
  silkscreen extent -1.37,-3.33 1.37,3.33
SW-SMD_4P-L6.0-W6.0-P4.50-LS9.2 [mm]
  rect 1.8x1.3 smd: 1(-4.2,2.25) 2(4.2,2.25) 3(-4.2,-2.25) 4(4.2,-2.25)
  silkscreen extent -3,-3 3,3
TF-SMD_DS1139-06-08SS4BSR [mm]
  rect 0.8x2 smd: 1(3.2,-1.6) 2(2.1,-1.6) 3(1,-1.6) 4(-0.1,-1.6) 5(-1.2,-1.6) 6(-2.3,-1.6) 7(-3.4,-1.6) 8(-4.5,-1.6)
  rect 1.8x2.2 smd: 9(-6.8,4.1) 10(-6.8,-4.1) 11(6.8,-4.1) 12(6.8,4.1)
  silkscreen extent -6.8,-6.65 6.8,7.75
TSOP-54_L22.2-W10.2-P0.80-LS11.8-BL [mm]
  oval 0.5x1.8 smd: 1(-10.4,-5.642) 2(-9.6,-5.642) 3(-8.8,-5.642) 4(-8,-5.642) 5(-7.2,-5.642) 6(-6.4,-5.642) 7(-5.6,-5.642) 8(-4.8,-5.642) 9(-4,-5.642) 10(-3.2,-5.642) 11(-2.4,-5.642) 12(-1.6,-5.642) 13(-0.8,-5.642) 14(0,-5.642) 15(0.8,-5.642) 16(1.6,-5.642) 17(2.4,-5.642) 18(3.2,-5.642) 19(4,-5.642) 20(4.8,-5.642) 21(5.6,-5.642) 22(6.4,-5.642) 23(7.2,-5.642) 24(8,-5.642) 25(8.8,-5.642) 26(9.6,-5.642) 27(10.4,-5.642) 28(10.4,5.642) 29(9.6,5.642) 30(8.8,5.642) 31(8,5.642) 32(7.2,5.642) 33(6.4,5.642) 34(5.6,5.642) 35(4.8,5.642) 36(4,5.642) 37(3.2,5.642) 38(2.4,5.642) 39(1.6,5.642) 40(0.8,5.642) 41(0,5.642) 42(-0.8,5.642) 43(-1.6,5.642) 44(-2.4,5.642) 45(-3.2,5.642) 46(-4,5.642) 47(-4.8,5.642) 48(-5.6,5.642) 49(-6.4,5.642) 50(-7.2,5.642) 51(-8,5.642) 52(-8.8,5.642) 53(-9.6,5.642) 54(-10.4,5.642)
  silkscreen extent -11.23,-5.79 11.19,4.65
USB-C-SMD_TYPE-C16PIN#1 [mm]
  oval 1x2.1 hole 0.6 slot 1.7 at 90 deg: 1(-4.32,1.787) 2(4.32,1.787)
  oval 1x1.8 hole 0.6 slot 1.4 at 90 deg: 3(-4.32,-2.362) 4(4.32,-2.362)
  rect 0.6x1.15 smd: A1B12(-3.2,2.362) A4B9(-2.4,2.362) B1A12(3.2,2.362) B4A9(2.4,2.362)
  rect 0.3x1.15 smd: A5(-1.25,2.362) A6(-0.25,2.362) A7(0.25,2.362) A8(1.25,2.362) B5(1.75,2.362) B6(0.75,2.362) B7(-0.75,2.362) B8(-1.75,2.362)
  Board Outline Layer circle w0.005: c2.89,1.288 r0.325
  Board Outline Layer circle w0.005: c-2.89,1.288 r0.325
  Board Outline Layer region: 2.89,1.613 3.031,1.581 3.144,1.491 3.207,1.36 3.207,1.216 3.144,1.085 3.031,0.995 2.89,0.963 2.89,0.963 2.749,0.995 2.636,1.085 2.573,1.216 2.573,1.36 2.636,1.491 2.749,1.581 2.89,1.613
  Board Outline Layer region: -2.89,1.613 -2.749,1.581 -2.636,1.491 -2.573,1.36 -2.573,1.216 -2.636,1.085 -2.749,0.995 -2.89,0.963 -2.89,0.963 -3.031,0.995 -3.144,1.085 -3.207,1.216 -3.207,1.36 -3.144,1.491 -3.031,1.581 -2.89,1.613
  Multi-Layer board cut-out: 2.89,1.613 3.031,1.581 3.144,1.491 3.207,1.36 3.207,1.216 3.144,1.085 3.031,0.995 2.89,0.963 2.89,0.963 2.749,0.995 2.636,1.085 2.573,1.216 2.573,1.36 2.636,1.491 2.749,1.581 2.89,1.613
  Multi-Layer board cut-out: -2.89,1.613 -2.749,1.581 -2.636,1.491 -2.573,1.36 -2.573,1.216 -2.636,1.085 -2.749,0.995 -2.89,0.963 -2.89,0.963 -3.031,0.995 -3.144,1.085 -3.207,1.216 -3.207,1.36 -3.144,1.491 -3.031,1.581 -2.89,1.613
  silkscreen extent -4.45,-5 4.45,0.52
USB-C-SMD_TYPE-C16PIN#2 [mm]
  oval 1x2.1 hole 0.6 slot 1.7 at 90 deg: 1(-4.32,1.787) 2(4.32,1.787)
  oval 1x1.8 hole 0.6 slot 1.4 at 90 deg: 3(-4.32,-2.362) 4(4.32,-2.362)
  rect 0.6x1.15 smd: A1B12(-3.2,2.362) A4B9(-2.4,2.362) B1A12(3.2,2.362) B4A9(2.4,2.362)
  rect 0.3x1.15 smd: A5(-1.25,2.362) A6(-0.25,2.362) A7(0.25,2.362) A8(1.25,2.362) B5(1.75,2.362) B6(0.75,2.362) B7(-0.75,2.362) B8(-1.75,2.362)
  Board Outline Layer circle w0.005: c2.89,1.288 r0.325
  Board Outline Layer circle w0.005: c-2.89,1.288 r0.325
  Board Outline Layer region: 3.215,1.288 3.183,1.147 3.093,1.034 2.962,0.971 2.818,0.971 2.687,1.034 2.597,1.147 2.565,1.288 2.565,1.288 2.597,1.429 2.687,1.542 2.818,1.605 2.962,1.605 3.093,1.542 3.183,1.429 3.215,1.288
  Board Outline Layer region: -2.565,1.288 -2.597,1.147 -2.687,1.034 -2.818,0.971 -2.962,0.971 -3.093,1.034 -3.183,1.147 -3.215,1.288 -3.215,1.288 -3.183,1.429 -3.093,1.542 -2.962,1.605 -2.818,1.605 -2.687,1.542 -2.597,1.429 -2.565,1.288
  Multi-Layer board cut-out: 3.215,1.288 3.183,1.147 3.093,1.034 2.962,0.971 2.818,0.971 2.687,1.034 2.597,1.147 2.565,1.288 2.565,1.288 2.597,1.429 2.687,1.542 2.818,1.605 2.962,1.605 3.093,1.542 3.183,1.429 3.215,1.288
  Multi-Layer board cut-out: -2.565,1.288 -2.597,1.147 -2.687,1.034 -2.818,0.971 -2.962,0.971 -3.093,1.034 -3.183,1.147 -3.215,1.288 -3.215,1.288 -3.183,1.429 -3.093,1.542 -2.962,1.605 -2.818,1.605 -2.687,1.542 -2.597,1.429 -2.565,1.288
  silkscreen extent -4.45,-5 4.45,0.52
WIRELM-SMD_ESP32-S3-WROOM-1 [mm]
  rect 1.5x0.9 smd: 1(-8.75,8.895) 2(-8.75,7.625) 3(-8.75,6.355) 4(-8.75,5.085) 5(-8.75,3.815) 6(-8.75,2.545) 7(-8.75,1.275) 8(-8.75,0.005) 9(-8.75,-1.265) 10(-8.75,-2.535) 11(-8.75,-3.805) 12(-8.75,-5.075) 13(-8.75,-6.345) 14(-8.75,-7.615) 27(8.75,-7.615) 28(8.75,-6.345) 29(8.75,-5.075) 30(8.75,-3.805) 31(8.75,-2.535) 32(8.75,-1.265) 33(8.75,0.005) 34(8.75,1.275) 35(8.75,2.545) 36(8.75,3.815) 37(8.75,5.085) 38(8.75,6.355) 39(8.75,7.625) 40(8.75,8.895)
  rect 0.9x1.5 smd: 15(-6.985,-8.895) 16(-5.715,-8.895) 17(-4.445,-8.895) 18(-3.175,-8.895) 19(-1.905,-8.895) 20(-0.635,-8.895) 21(0.635,-8.895) 22(1.905,-8.895) 23(3.175,-8.895) 24(4.445,-8.895) 25(5.715,-8.895) 26(6.985,-8.865)
  rect 0.9x0.9 smd: 41(-2.9,-0.225) 41(-2.9,1.175) 41(-2.9,2.575) 41(-1.5,2.575) 41(-1.5,-0.225) 41(-1.5,1.175) 41(-0.1,2.575) 41(-0.1,1.175) 41(-0.1,-0.225)
  silkscreen extent -9,-9.14 9.02,16.39

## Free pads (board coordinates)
  round 1.524 hole 0.914: 1(89.467,95.563) 1(100.389,118.677)
  round 0.08 smd: 55(85.271,118.491) 55(86.292,118.169) 55(87.15,148.289) 55(87.181,87.943) 55(87.181,117.788) 55(89.194,84.406) 55(89.213,83.498) 55(91.753,134.298) 55(114.861,94.892) 55(116.341,96.923) 55(133.577,93.091) 55(134.977,93.052)
  round 0.08 smd far side: 55(95.182,118.55) 55(101.786,127.673) 55(102.929,127.694) 55(103.056,139.505) 55(103.564,128.456) 55(104.453,129.091)

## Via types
v1: diameter 0.4, hole 0.3, Top Layer to Bottom Layer, 387 vias
v2: diameter 0.5, hole 0.3, Top Layer to Bottom Layer, 36 vias
v3: diameter 1, hole 0.5, Top Layer to Bottom Layer, 2 vias

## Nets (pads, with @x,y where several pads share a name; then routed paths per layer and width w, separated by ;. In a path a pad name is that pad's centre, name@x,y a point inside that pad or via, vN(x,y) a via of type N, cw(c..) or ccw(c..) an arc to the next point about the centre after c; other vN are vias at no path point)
$1N8318: C15.2 U5.43 | length 1.4
  Top Layer w0.254: C15.2@122.428,150.427 122.665,150.19 U5.43@122.665,149.084
$1N8986: C16.2 U5.49 | length 1.5
  Top Layer w0.254: C16.2@117.545,150.416 117.865,150.096 U5.49@117.865,149.084
$1N9039: C14.1 U5.27 | length 0.7
  Top Layer w0.254: U5.27@134.665,137.8 134.738,137.727 C14.1@135.373,137.727
$1N9091: C13.1 U5.14 | length 1.5
  Top Layer w0.254: C13.1@124.265,136.33 U5.14@124.265,137.8
$1N9142: C12.1 U5.9 | length 1.4
  Top Layer w0.254: 119.82,136.584 120.265,137.029 U5.9@120.265,137.8
$1N9192: C11.1 U5.3 | length 1.4
  Top Layer w0.254: C11.1@115.316,136.457 115.465,136.606 U5.3@115.465,137.8
$1N9241: C10.1 U5.1 | length 1.5
  Top Layer w0.254: C10.1@113.865,136.457 U5.1@113.865,137.927
$1N9341: C8.1 C10.2 C11.2 C12.2 C13.2 C14.2 C15.1 C16.1 R1.2 | length 66.2
  Top Layer w0.254: C10.2@114.3,136.457 114.613,136.144 v1(114.613,135.97) 114.926,136.283 C11.2@114.926,136.457 ; v1(116.802,151.219) 117.269,150.752 C16.1@117.269,150.692 ; v1(119.058,135.822) C12.2@119.428,136.192 ; v1(121.558,150.848) 121.617,150.848 C15.1@122.038,150.427 ; v1(123.63,134.298) 123.757,134.171 125.916,134.171 126.932,135.187 v1(127.059,135.187) ; v1(124.265,135.314) C13.2@124.265,135.881 ; v1(125.154,152.205) 126.603,152.205 R1.2@126.678,152.13 ; C14.2@135.763,137.727 v1(135.763,138.235) ; C8.1@136.711,144.315 137.457,143.569 v1(138.235,143.569)
  Bottom Layer w0.254: v1(114.613,135.97) 114.761,135.822 v1(119.058,135.822) 122.106,135.822 v1(123.63,134.298) 123.63,134.679 v1(124.265,135.314) ; v1(116.802,151.219) 121.187,151.219 v1(121.558,150.848) 123.797,150.848 v1(125.154,152.205) 135.763,141.596 v1(135.763,138.235) ; v1(127.059,135.187) 132.715,135.187 v1(135.763,138.235) ; v1(138.235,143.569) 138.235,140.707 v1(135.763,138.235)
$1N9437: R1.1 U5.37 | length 2.5
  Top Layer w0.254: R1.1@126.678,151.264 127.465,150.477 U5.37@127.465,149.084
$1N11348: R2.1 U5.38 | length 19.3
  Top Layer w0.1: R2.1@109.839,144.585 123.122,144.585 126.678,148.141 126.678,149.071 U5.38@126.665,149.084
$1N11975: R7.1 U2.3 | length 1.5
  Top Layer w0.254: U2.3@87.938,99.132 87.943,99.127 R7.1@87.943,97.647
$1N12553: R10.2 USB1.B5 | length 1.7
  Top Layer w0.254: USB1.B5@83.574,86.447 84.804,86.447 R10.2@85.157,86.8
$1N12557: R9.2 USB1.A5 | length 2
  Top Layer w0.254: USB1.A5@83.574,89.447 84.612,89.447 R9.2@85.276,90.11
$1N14416: C18.2 L1.1 U6.5 | length 7.6
  Top Layer w0.254: L1.1@89.134,88.197 89.134,90.356 88.705,90.785 88.705,93.437 88.987,93.72 89.207,93.72 C18.2@89.213,93.726 90.725,93.726 U6.5@90.784,93.785
$1N14459: C18.1 U6.6 | length 1.8
  Top Layer w0.254: C18.1@89.213,93.336 89.714,92.835 U6.6@90.784,92.835
$1N14567: C19.1 R11.1 R12.2 U6.1 | length 11.6
  Top Layer w0.254: U6.1@93.484,92.835 97.467,92.835 C19.1@98.611,91.691 101.605,91.691 R11.1@101.659,91.744 104.563,91.744 R12.2@104.58,91.761
$1N16832: C24.2 L2.1 U7.5 | length 5.3
  Top Layer w0.254: C24.2@122.995,94.987 122.174,94.166 U7.5@121.678,94.166 121.684,94.16 L2.1@125.313,94.16
$1N16833: C24.1 U7.6 | length 1.4
  Top Layer w0.254: U7.6@121.678,95.116 121.933,95.371 122.989,95.371 C24.1@122.995,95.377
$1N16834: C25.1 R14.2 R15.1 U7.1 | length 30.7
  Top Layer w0.254: U7.1@118.978,95.116 119.272,95.116 120.328,94.06 120.328,93.321 128.627,85.022 135.695,85.022 136.563,85.89 R14.2@136.563,89.642 135.547,89.642 R15.1@135.03,89.125 134.977,89.072 C25.1@134.977,86.458
$1N17349: C29.2 C30.2 C31.1 C32.1 | length 3.8
  Top Layer w0.254: C30.2@117.221,100.389 118.296,99.314 C32.1@118.296,98.013 117.385,98.013 C29.2@117.348,97.976
$1N29790: R26.2 U2.5 | length 57.9
  Top Layer w0.1: v1(78.029,139.251) 78.291,139.513 R26.2@78.291,140.088 ; U2.5@90.478,99.132 90.483,99.127 v1(90.483,98.103)
  Bottom Layer w0.1: v1(78.029,139.251) 77.91,139.132 77.91,138.819 77.781,138.691 77.781,138.419 77.91,138.291 77.91,138.019 77.781,137.891 77.781,137.619 77.91,137.491 77.91,137.219 77.781,137.091 77.781,136.819 77.91,136.691 77.91,136.419 77.781,136.291 77.781,136.019 77.91,135.891 77.91,135.619 77.781,135.491 77.781,135.219 77.91,135.091 77.91,134.819 77.781,134.691 77.781,134.419 77.91,134.291 77.91,97.214 78.164,96.96 87.942,96.96 89.085,98.103 v1(90.483,98.103)
$1N29833: R27.2 U2.6 | length 59.2
  Top Layer w0.1: v1(78.708,139.215) 78.708,139.362 R27.2@79.434,140.088 ; v1(91.748,98.103) U2.6@91.748,99.132
  Bottom Layer w0.1: v1(78.708,139.215) 78.418,138.925 78.418,138.654 78.347,138.583 78.21,138.583 78.139,138.512 78.139,138.254 78.21,138.183 78.347,138.183 78.418,138.112 78.418,137.854 78.347,137.783 78.21,137.783 78.139,137.712 78.139,137.454 78.21,137.383 78.347,137.383 78.418,137.312 78.418,137.054 78.347,136.983 78.21,136.983 78.139,136.912 78.139,136.654 78.21,136.583 78.347,136.583 78.418,136.512 78.418,136.254 78.347,136.183 78.21,136.183 78.139,136.112 78.139,135.854 78.21,135.783 78.347,135.783 78.418,135.712 78.418,135.454 78.347,135.383 78.21,135.383 78.139,135.312 78.139,135.054 78.21,134.983 78.347,134.983 78.418,134.912 78.418,134.654 78.347,134.583 78.21,134.583 78.139,134.512 78.139,134.254 78.21,134.183 78.347,134.183 78.418,134.112 78.418,133.854 78.347,133.783 78.21,133.783 78.139,133.712 78.139,133.454 78.21,133.383 78.347,133.383 78.418,133.312 78.418,133.09 78.347,133.019 78.21,133.019 78.139,132.949 78.139,132.69 78.21,132.619 78.347,132.619 78.418,132.549 78.418,132.29 78.347,132.219 78.21,132.219 78.139,132.149 78.139,131.89 78.21,131.819 78.347,131.819 78.418,131.749 78.418,131.49 78.347,131.419 78.21,131.419 78.139,131.349 78.139,131.09 78.21,131.019 78.347,131.019 78.418,130.949 78.418,100.643 80.196,98.865 90.986,98.865 v1(91.748,98.103)
$1N29916: R29.2 U2.9 | length 59.1
  Top Layer w0.1: v1(80.019,139.046) 80.374,139.046 81.415,140.088 R29.2@81.72,140.088 ; v1(94.166,100.897) 95.558,99.505 U2.9@95.558,99.132
  Bottom Layer w0.1: v1(80.019,139.046) 79.817,138.844 79.76,138.844 79.488,138.572 79.488,138.275 79.559,138.204 79.744,138.204 79.815,138.134 79.815,137.875 79.744,137.804 79.559,137.804 79.488,137.734 79.488,137.475 79.559,137.404 79.744,137.404 79.815,137.334 79.815,137.075 79.744,137.004 79.559,137.004 79.488,136.934 79.488,136.675 79.559,136.604 79.744,136.604 79.815,136.534 79.815,136.275 79.744,136.204 79.559,136.204 79.488,136.134 79.488,135.875 79.559,135.804 79.744,135.804 79.815,135.734 79.815,135.475 79.744,135.404 79.559,135.404 79.488,135.334 79.488,135.075 79.559,135.004 79.744,135.004 79.815,134.934 79.815,134.675 79.744,134.604 79.559,134.604 79.488,134.534 79.488,134.32 79.559,134.25 79.744,134.25 79.815,134.179 79.815,133.92 79.744,133.85 79.559,133.85 79.488,133.779 79.488,133.52 79.559,133.45 79.744,133.45 79.815,133.379 79.815,133.12 79.744,133.05 79.559,133.05 79.488,132.979 79.488,104.145 82.736,100.897 v1(94.166,100.897)
$1N29959: R30.2 U2.12 | length 59.5
  Top Layer w0.1: v1(80.958,138.997) 81.772,138.997 R30.2@82.863,140.088 ; v1(91.499,102.421) 98.357,102.421 99.368,101.41 U2.12@99.368,99.132
  Bottom Layer w0.1: v1(80.958,138.997) 80.538,138.997 80.186,138.644 80.186,138.635 80.142,138.591 80.142,105.65 83.371,102.421 v1(91.499,102.421)
$1N30002: R31.2 U2.23 | length 58.9
  Top Layer w0.1: v1(81.339,112.073) 101.151,112.073 102.167,111.057 U2.23@103.061,111.057 ; v1@82.228,138.997 82.915,138.997 R31.2@84.006,140.088
  Bottom Layer w0.1: v1(81.339,112.073) 80.742,112.669 80.742,128.007 80.672,128.077 80.442,128.077 80.371,128.148 80.371,128.407 80.442,128.477 80.672,128.477 80.742,128.548 80.742,128.807 80.672,128.877 80.442,128.877 80.371,128.948 80.371,129.207 80.442,129.277 80.672,129.277 80.742,129.348 80.742,129.607 80.672,129.677 80.442,129.677 80.371,129.748 80.371,130.007 80.442,130.077 80.672,130.077 80.742,130.148 80.742,130.407 80.672,130.477 80.442,130.477 80.371,130.548 80.371,130.807 80.442,130.877 80.672,130.877 80.742,130.948 80.742,131.207 80.672,131.277 80.442,131.277 80.371,131.348 80.371,131.607 80.442,131.677 80.672,131.677 80.742,131.748 80.742,132.007 80.672,132.077 80.442,132.077 80.371,132.148 80.371,132.407 80.442,132.477 80.672,132.477 80.742,132.548 80.742,132.807 80.672,132.877 80.442,132.877 80.371,132.948 80.371,133.207 80.442,133.277 80.672,133.277 80.742,133.348 80.742,133.607 80.672,133.677 80.442,133.677 80.371,133.748 80.371,134.007 80.442,134.077 80.672,134.077 80.742,134.148 80.742,134.407 80.672,134.477 80.442,134.477 80.371,134.548 80.371,134.807 80.442,134.877 80.672,134.877 80.742,134.948 80.742,135.207 80.672,135.277 80.442,135.277 80.371,135.348 80.371,135.607 80.442,135.677 80.672,135.677 80.742,135.748 80.742,136.545 80.342,136.946 80.342,138.229 80.621,138.508 81.47,138.508 81.903,138.941 v1(82.284,138.941)
$1N30085: R34.2 U2.25 | length 59.4
  Top Layer w0.1: v1@84.387,138.743 85.074,138.743 86.292,139.961 R34.2@86.292,140.088 ; v1(84.895,113.724) 85.022,113.597 85.83,113.597 85.901,113.668 85.901,113.907 85.971,113.978 86.23,113.978 86.301,113.907 86.301,113.668 86.371,113.597 86.63,113.597 86.701,113.668 86.701,113.907 86.771,113.978 87.03,113.978 87.101,113.907 87.101,113.668 87.171,113.597 87.43,113.597 87.501,113.668 87.501,113.907 87.571,113.978 87.83,113.978 87.901,113.907 87.901,113.668 87.971,113.597 88.23,113.597 88.301,113.668 88.301,113.907 88.371,113.978 88.63,113.978 88.701,113.907 88.701,113.668 88.771,113.597 89.03,113.597 89.101,113.668 89.101,113.907 89.171,113.978 89.43,113.978 89.501,113.907 89.501,113.668 89.571,113.597 U2.25@103.061,113.597
  Bottom Layer w0.1: v1(84.379,138.75) 82.355,136.725 82.355,136.405 82.426,136.334 82.792,136.334 82.863,136.263 82.863,136.005 82.792,135.934 82.426,135.934 82.355,135.863 82.355,135.605 82.426,135.534 82.782,135.534 82.852,135.463 82.852,135.205 82.782,135.134 82.426,135.134 82.355,135.063 82.355,134.805 82.426,134.734 82.791,134.734 82.861,134.663 82.861,134.405 82.791,134.334 82.426,134.334 82.355,134.263 82.355,134.005 82.426,133.934 82.782,133.934 82.852,133.863 82.852,133.605 82.782,133.534 82.426,133.534 82.355,133.463 82.355,133.205 82.426,133.134 82.827,133.134 82.897,133.063 82.897,132.805 82.827,132.734 82.426,132.734 82.355,132.663 82.355,132.405 82.426,132.334 82.853,132.334 82.924,132.263 82.924,132.005 82.853,131.934 82.426,131.934 82.355,131.863 82.355,131.605 82.426,131.534 82.898,131.534 82.969,131.463 82.969,131.205 82.898,131.134 82.426,131.134 82.355,131.063 82.355,130.849 82.426,130.779 82.905,130.779 82.976,130.708 82.976,130.449 82.905,130.379 82.426,130.379 82.355,130.308 82.355,130.049 82.426,129.979 82.905,129.979 82.976,129.908 82.976,129.649 82.905,129.579 82.426,129.579 82.047,129.2 82.047,116.572 v1(84.895,113.724)
$1N30089: R32.2 U2.24 | length 59.6
  Top Layer w0.1: v1(83.371,138.87) 83.931,138.87 R32.2@85.149,140.088 ; v1(84.641,113.089) 101.024,113.089 101.786,112.327 U2.24@103.061,112.327
  Bottom Layer w0.1: v1(83.371,138.87) 82.809,138.308 81.808,138.308 81.212,137.712 81.212,135.98 81.283,135.909 81.776,135.909 81.847,135.839 81.847,135.58 81.776,135.509 81.283,135.509 81.212,135.439 81.212,135.18 81.283,135.109 81.776,135.109 81.847,135.039 81.847,134.78 81.776,134.709 81.283,134.709 81.212,134.639 81.212,134.38 81.283,134.309 81.776,134.309 81.847,134.239 81.847,133.98 81.776,133.909 81.283,133.909 81.212,133.839 81.212,133.58 81.283,133.509 81.776,133.509 81.847,133.439 81.847,133.18 81.776,133.109 81.283,133.109 81.212,133.039 81.212,132.78 81.283,132.709 81.776,132.709 81.847,132.639 81.847,132.38 81.776,132.309 81.283,132.309 81.212,132.239 81.212,131.98 81.283,131.909 81.776,131.909 81.847,131.839 81.847,131.58 81.776,131.509 81.283,131.509 81.212,131.439 81.212,131.18 81.283,131.109 81.776,131.109 81.847,131.039 81.847,130.78 81.776,130.709 81.283,130.709 81.212,130.639 81.212,130.38 81.283,130.309 81.776,130.309 81.847,130.239 81.847,129.98 81.776,129.909 81.283,129.909 81.212,129.839 81.212,129.58 81.283,129.509 81.776,129.509 81.847,129.439 81.847,129.18 81.776,129.109 81.283,129.109 81.212,129.039 81.212,116.518 v1(84.641,113.089)
$1N30093: R28.2 U2.7 | length 59.1
  Top Layer w0.1: v1(79.34,139.124) 79.401,139.124 80.365,140.088 R28.2@80.577,140.088 ; U2.7@93.018,99.132 v1(93.018,100.135)
  Bottom Layer w0.1: v1(79.34,139.124) 78.672,138.455 78.672,138.211 78.743,138.141 78.855,138.141 78.926,138.07 78.926,137.811 78.855,137.741 78.743,137.741 78.672,137.67 78.672,137.411 78.743,137.341 78.855,137.341 78.926,137.27 78.926,137.011 78.855,136.941 78.743,136.941 78.672,136.87 78.672,136.611 78.743,136.541 78.855,136.541 78.926,136.47 78.926,136.211 78.855,136.141 78.743,136.141 78.672,136.07 78.672,135.811 78.743,135.741 78.855,135.741 78.926,135.67 78.926,135.411 78.855,135.341 78.743,135.341 78.672,135.27 78.672,135.011 78.743,134.941 78.855,134.941 78.926,134.87 78.926,134.611 78.855,134.541 78.743,134.541 78.672,134.47 78.672,134.211 78.743,134.141 78.855,134.141 78.926,134.07 78.926,133.811 78.855,133.741 78.743,133.741 78.672,133.67 78.672,133.411 78.743,133.341 78.855,133.341 78.926,133.27 78.926,133.011 78.855,132.941 78.743,132.941 78.672,132.87 78.672,132.62 78.743,132.549 78.982,132.549 79.053,132.478 79.053,132.22 78.982,132.149 78.743,132.149 78.672,132.078 78.672,131.82 78.743,131.749 78.982,131.749 79.053,131.678 79.053,131.42 78.982,131.349 78.743,131.349 78.672,131.278 78.672,101.405 79.942,100.135 v1(93.018,100.135)
$1N33205: P1.8 R35.1 | length 1.9
  Top Layer w0.1: R35.1@110.041,165.084 110.081,165.124 P1.8@110.081,166.951
$1N60668: C64.1 U11.6 | length 1.4
  Top Layer w0.1: U11.6@104.713,86.833 105.411,87.531 105.411,87.555 105.529,87.674 105.554,87.674 105.637,87.757 C64.1@105.723,87.757
$1N60669: C64.2 L3.1 U11.5 | length 3.6
  Top Layer w0.1: U11.5@104.713,85.883 L3.1@106.389,85.883 ; C64.2@105.723,87.367 105.723,86.549 L3.1@106.389,85.883 ; L3.1@106.488,85.784 L3.1@106.389,85.883
$1N60670: C65.1 R40.2 R41.1 U11.1 | length 7.6
  Top Layer w0.1: U11.1@102.013,86.833 102.461,86.385 102.646,86.385 102.765,86.266 102.765,86.081 103.572,85.273 R40.2@103.572,79.942
$1N63749: R43.1 USB2.A5 | length 6.1
  Top Layer w0.1: R43.1@92.252,81.466 92.379,81.339 v1(93.15,81.339) ; v1(96.726,82.482) USB2.A5@96.726,83.574
  Bottom Layer w0.1: v1(93.15,81.339) 95.583,81.339 v1(96.726,82.482)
